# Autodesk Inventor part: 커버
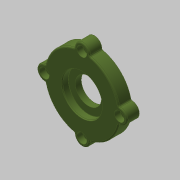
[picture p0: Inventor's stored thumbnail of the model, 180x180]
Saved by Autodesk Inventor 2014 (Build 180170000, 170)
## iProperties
Created: 2016-06
Part Number: 커버
Material: 알루미늄 6061
Document SubType Name: Modeling
Designer: mduedu
Density: 2.71 g/cm^3
Appearance: Olive Green
Author: mduedu
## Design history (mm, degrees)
sketch "스케치1"
  geometry: C1 r 30 at (0, 0); 1 further point
  constraints: 1 centre point, 1 coincident
  dimensions: "d0" = 60 diameter of C1
extrude "돌출1" new body sketch "스케치1" distance "d2" = 10; taper "d3" = 0 deg
sketch "스케치5"
  geometry: C1 r 6 at (0, 30); 2 further points
  constraints: 2 vertical alignment, 1 centre point, 1 other
  dimensions: "d61" = 12 diameter of C1
extrude "돌출3" join sketch "스케치5" stored distance "d62" = 10; taper "d63" = 0 deg
sketch "스케치2"
  geometry: C1 r 21 at (0, 0); 1 further point
  constraints: 1 centre point, 1 coincident
  dimensions: "d4" = 42 diameter of C1
extrude "돌출2" join sketch "스케치2" distance "d6" = 3; taper "d7" = 0 deg
hole "구멍1" diameter "d11" = 35; stored, may be unused: countersink angle "d15" = 90 deg, drill point angle "d17" = 0 deg; dims "d9" = 10, "d10" = 10, "d12" = 6, "d13" = 4, "d14" = 2, "d16" = 3
hole "구멍2" diameter "d20" = 32; stored, may be unused: countersink angle "d24" = 90 deg, drill point angle "d26" = 0 deg; dims "d21" = 6, "d22" = 4, "d23" = 2, "d25" = 5.2, "d67" = 10, "d68" = 10
hole "구멍3" diameter "d29" = 21; stored, may be unused: countersink angle "d33" = 90 deg, drill point angle "d35" = 0 deg; dims "d27" = 10, "d28" = 10, "d30" = 6, "d31" = 4, "d32" = 2, "d34" = 5
fillet "모깎기2" dims "d36" = 3
fillet "모깎기3" dims "d37" = 0.1
chamfer "모따기1" distance "d38" = 0.75; stored, may be unused: second distance "d39" = 2, angle "d40" = 30 deg
chamfer "모따기2" distance "d42" = 0.5; stored, may be unused: second distance "d43" = 2, angle "d44" = 30 deg
sketch "스케치6"
  geometry: A1 r 30 centre (0, 0) between (29.4, 5.97) and (5.97, 29.4) reference; 3 further points
  constraints: 2 vertical alignment, 1 coincident, 3 other
hole "구멍5" sketch "스케치6" at (0, 30) diameter "d69" = 4.5; stored, may be unused: countersink angle "d73" = 90 deg, drill point angle "d75" = 118 deg; dims "d70" = 6, "d71" = 8, "d72" = 4.6, "d74" = 8
fillet "모깎기5" dims "d79" = 1
fillet "모깎기6" dims "d80" = 1
node "솔리드1"
pattern_circular "원형 패턴1" dims angle "d65" = 360 deg
pattern_circular "원형 패턴2" dims angle "d77" = 360 deg
node "투영된 루프1"
